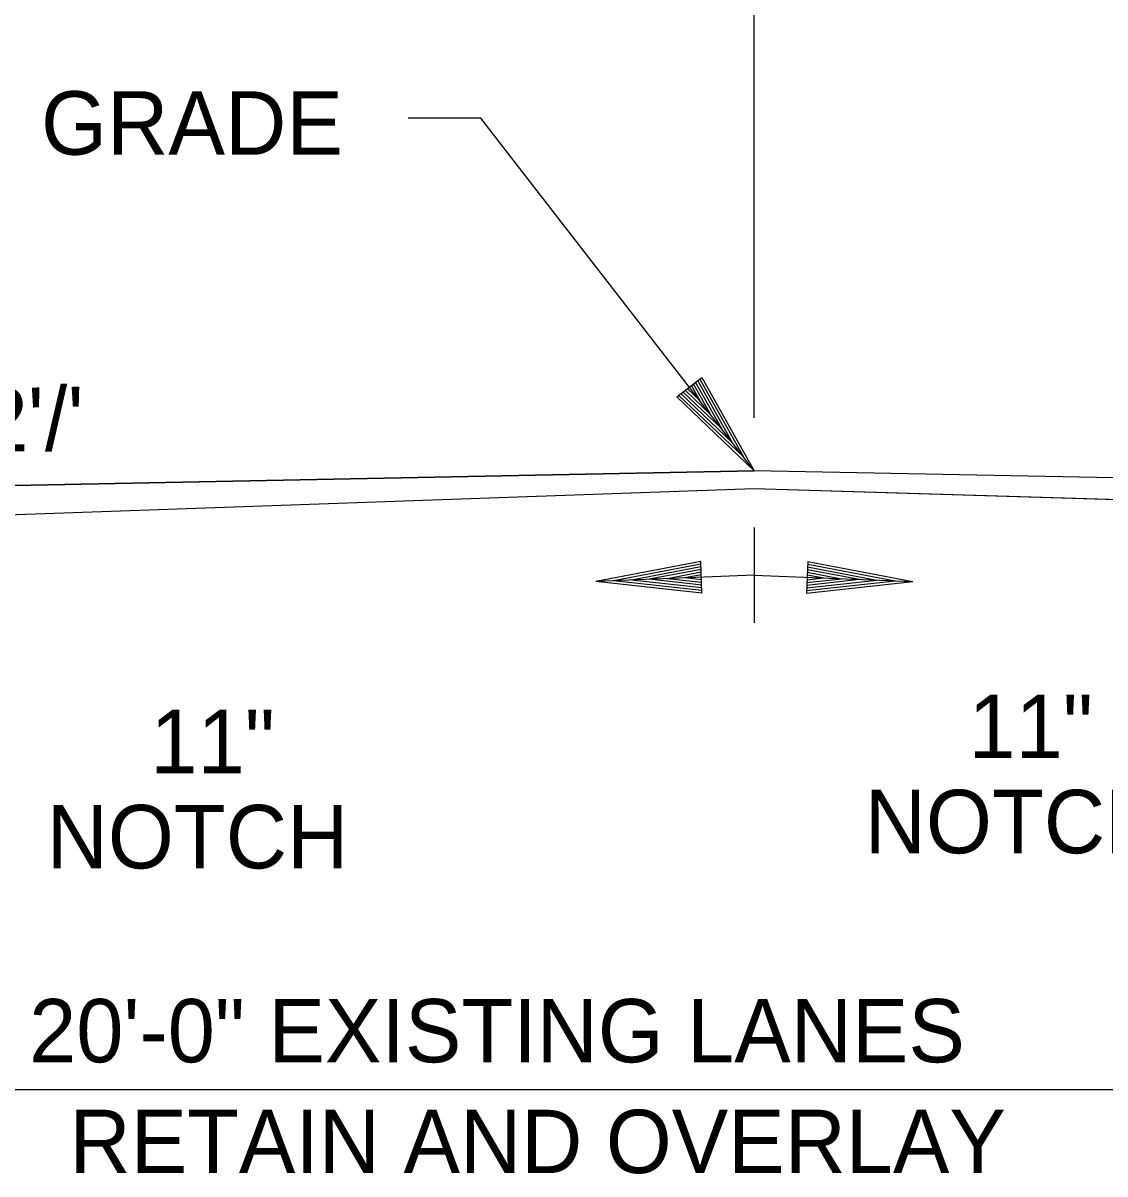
# Model space of a CAD drawing. Extents: x 138 to 3619, y -519 to 1449.
# Drawn here: x 538.9 to 641.1, y -391.6 to -282.8 of the extents above; entities that cross this region are included whole.
import ezdxf

# ---------------------------------------------------------------- set-up
doc = ezdxf.new("R2010")
doc.units = 0
for name, color, linetype in [('R_Annotation', 7, 'Continuous'), ('R_Centerline', 7, 'Continuous'), ('R_Dimension', 7, 'Continuous')]:
    doc.layers.add(name, color=color, linetype=linetype)

msp = doc.modelspace()

# ---------------------------------------------------------------- linework, layer by layer
at = {"layer": 'R_Annotation'}
for p in [(498, -327.31), (718, -327.31)]:
    msp.add_line(p, (608, -325.11), dxfattribs=at)
at = {"layer": 'R_Centerline'}
msp.add_line((608, -320.11), (608, -272.33), dxfattribs=at)
at = {"layer": 'R_Dimension'}
for p, q in [((600.69, -318.13), (603.06, -316.29)), ((602.66, -316.6), (605.92, -322.43)), ((602.86, -316.45), (606.98, -323.79)), ((603.06, -316.29), (608, -325.11)), ((601.28, -317.67), (604.9, -321.12)), ((601.49, -317.51), (603.86, -319.78)), ((601.69, -317.36), (602.84, -318.46)), ((602.06, -317.07), (602.84, -318.46)), ((602.26, -316.91), (603.86, -319.78)), ((602.46, -316.76), (604.9, -321.12)), ((600.69, -318.13), (608, -325.11)), ((600.88, -317.98), (606.98, -323.79)), ((601.09, -317.82), (605.92, -322.43)), ((608, -325.11), (498, -327.31)), ((608, -325.11), (498, -327.31)), ((608, -325.11), (608, -325.11)), ((688, -326.71), (608, -325.11)), ((608, -326.78), (608, -326.78)), ((608, -326.78), (688, -329.21)), ((608, -330.48), (608, -339.47)), ((602.94, -333.68), (593.01, -335.58)), ((602.95, -333.93), (594.68, -335.51)), ((603.06, -336.68), (602.94, -333.68)), ((613.06, -333.68), (612.94, -336.67)), ((613.05, -333.93), (621.32, -335.51)), ((613.06, -333.68), (622.99, -335.58)), ((608, -334.98), (593.01, -335.58)), ((602.96, -334.18), (596.4, -335.44)), ((602.97, -334.43), (598.06, -335.37)), ((602.98, -334.69), (599.76, -335.31)), ((603, -334.94), (601.43, -335.24)), ((608, -334.98), (622.99, -335.58)), ((613, -334.94), (614.57, -335.24)), ((613.01, -334.69), (616.24, -335.31)), ((613.02, -334.43), (617.94, -335.37)), ((613.03, -334.18), (619.6, -335.44)), ((603.06, -336.68), (593.01, -335.58)), ((603.05, -336.43), (594.68, -335.51)), ((603.04, -336.17), (596.4, -335.44)), ((603.03, -335.92), (598.06, -335.37)), ((603.02, -335.66), (599.76, -335.31)), ((603.01, -335.41), (601.43, -335.24)), ((612.94, -336.67), (622.99, -335.58)), ((612.95, -336.43), (621.32, -335.51)), ((612.96, -336.17), (619.6, -335.44)), ((612.97, -335.92), (617.94, -335.37)), ((612.98, -335.67), (616.24, -335.31)), ((612.99, -335.41), (614.57, -335.24)), ((498, -383.61), (688, -383.61))]:
    msp.add_line(p, q, dxfattribs=at)
for points in [[(608, -325.11), (582.15, -291.79), (575.29, -291.79)], [(498, -330.65), (608, -326.78), (687.95, -329.21)], [(498, -330.65), (608, -326.78), (608, -326.78)]]:
    msp.add_lwpolyline(points, dxfattribs=at)

# ---------------------------------------------------------------- texts
at = {"layer": 'R_Annotation'}
for s, height, p in [('PROFILE GRADE', 6, (504.03, -295.23)), ('11" ', 6, (628.24, -352.27)), ('11" ', 6, (550.92, -353.7)), ('NOTCH', 6, (618.43, -361.27)), ('NOTCH', 6, (541.11, -362.7)), ('20\'-0" EXISTING LANES', 5.985, (539.47, -381.03)), ('RETAIN AND OVERLAY', 5.985, (543.28, -391.5))]:
    msp.add_text(s, height=height, dxfattribs=at).set_placement(p)
msp.add_text("0.02'/'", height=6, rotation=1.0613, dxfattribs=at).set_placement((523.81, -323.54))

doc.saveas('drawing.dxf')
